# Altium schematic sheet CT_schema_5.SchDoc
size 573 x 363 mm
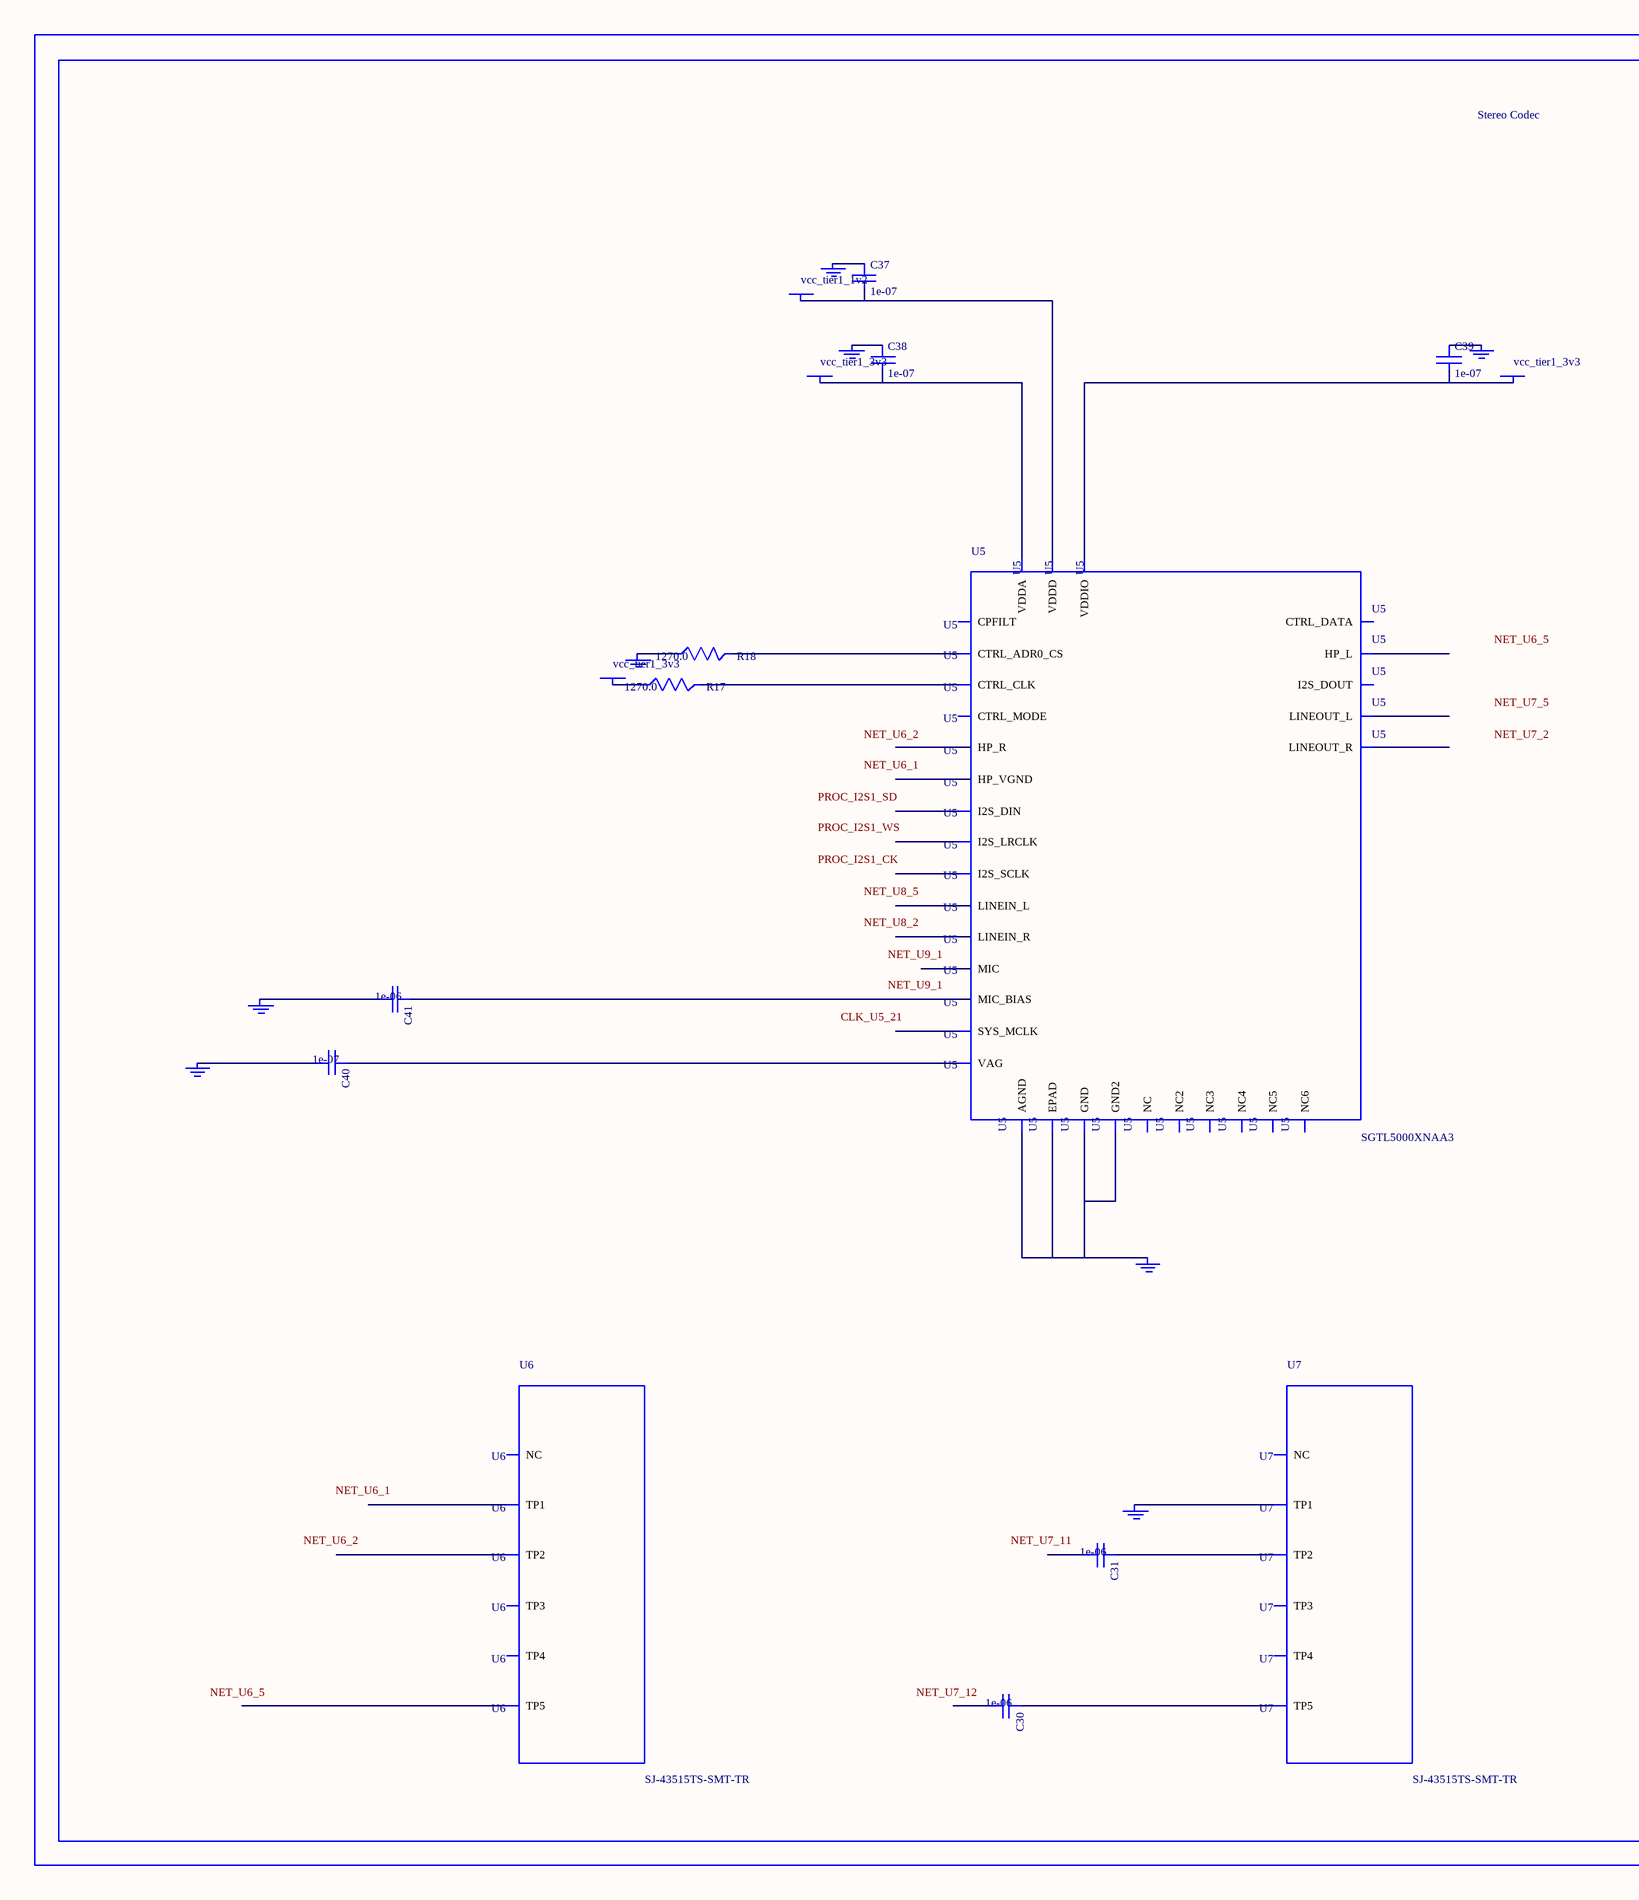
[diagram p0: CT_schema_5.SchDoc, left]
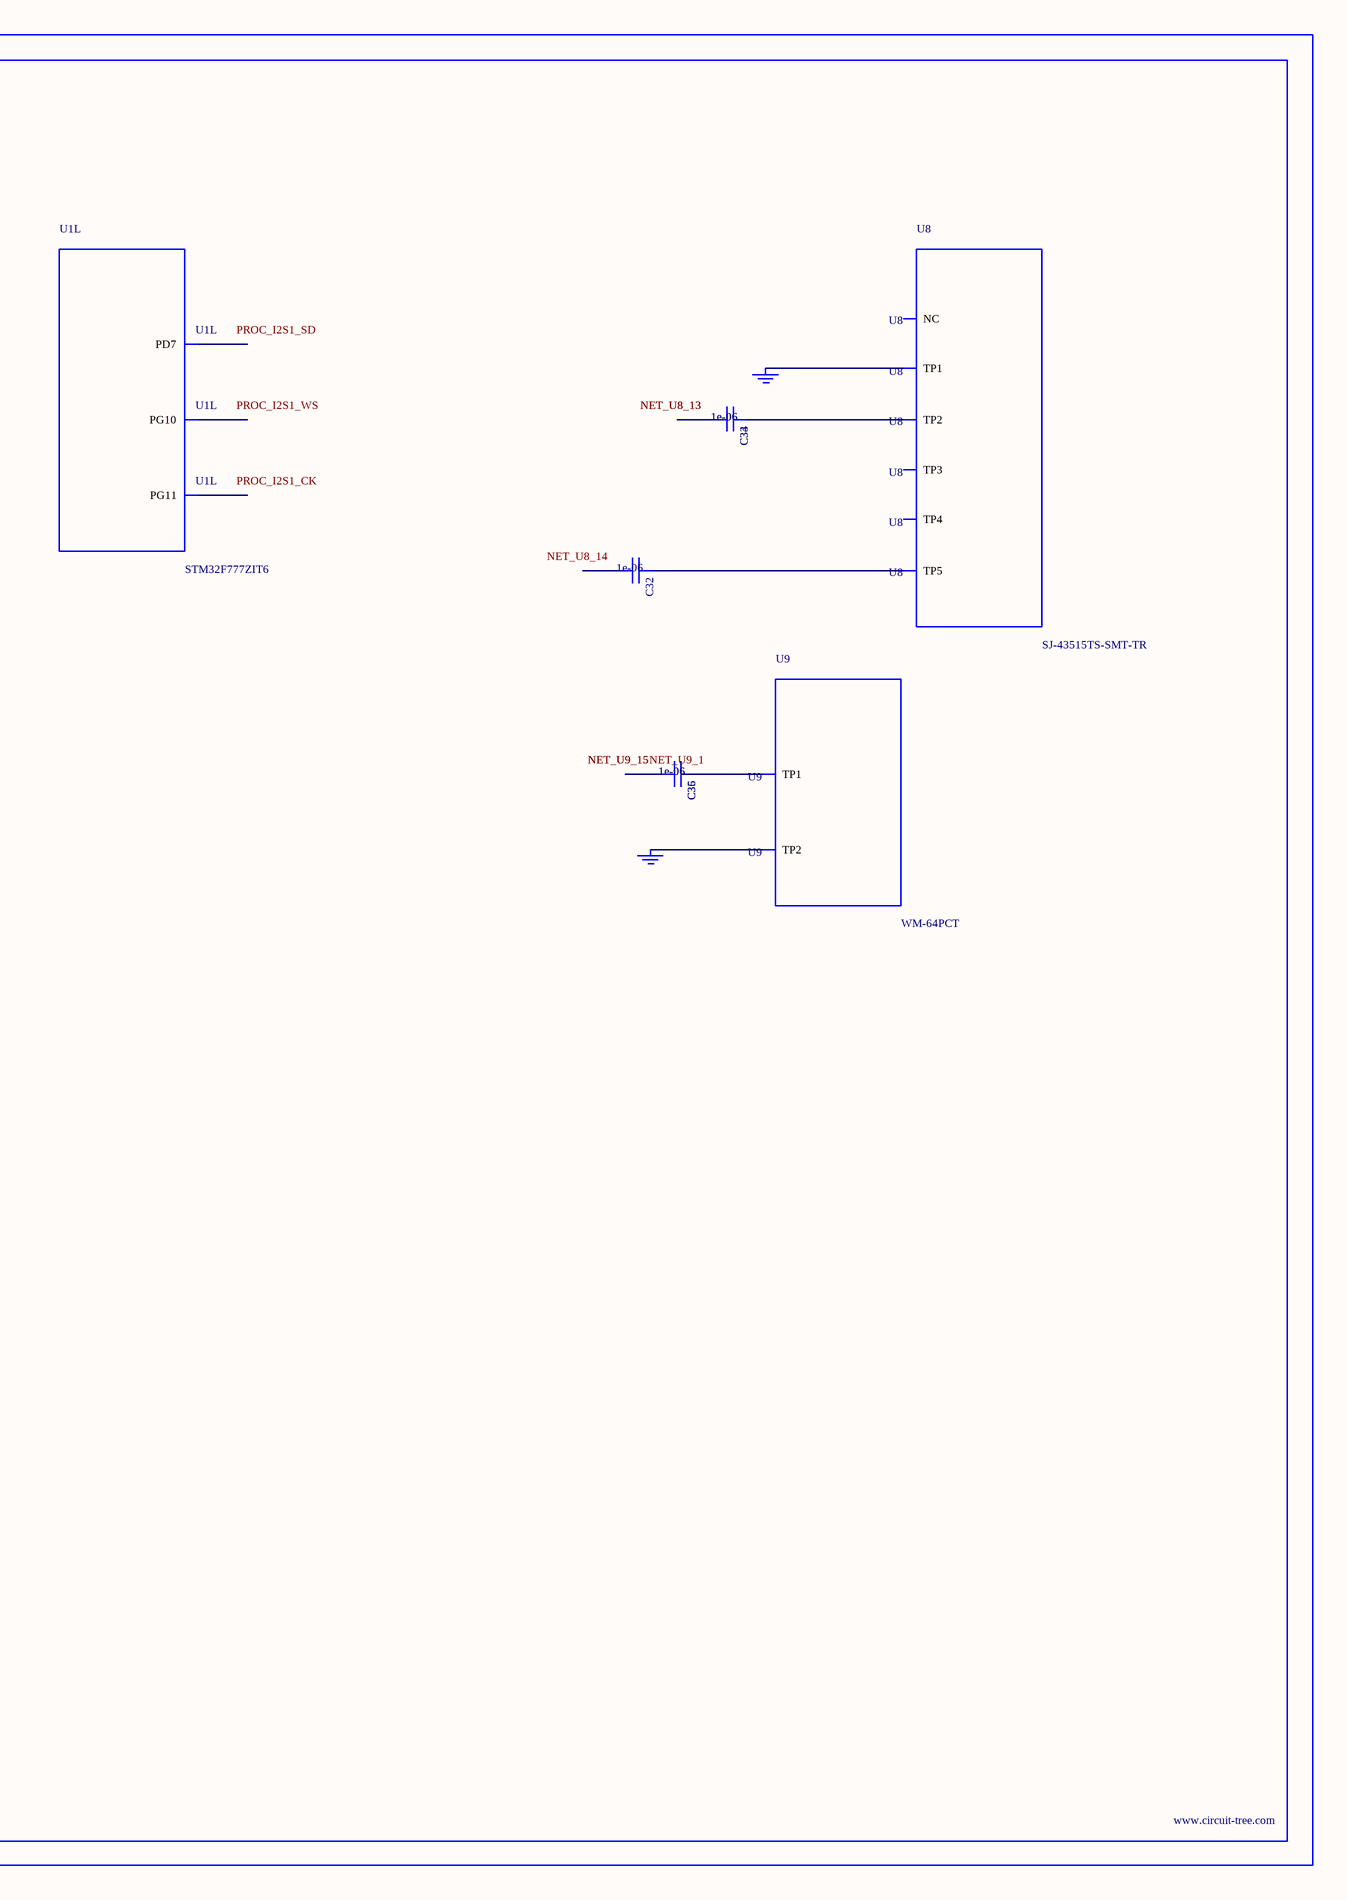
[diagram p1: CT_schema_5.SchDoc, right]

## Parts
BORDER4  (no value)
C30  1e-06  [C0603]
C31  1e-06  [C0603]
C32  1e-06  [C0603]
C33  1e-06  [C0603]
C34  1e-06  [C0603]
C35  1e-06  [C0603]
C36  1e-06  [C0603]
C37  1e-07  [C0402]
C38  1e-07  [C0402]
C39  1e-07  [C0402]
C40  1e-07  [C0402]
C41  1e-06  [C0603]
GND_INSTANCE_4_0  (no value)
GND_INSTANCE_4_1  (no value)
GND_INSTANCE_4_2  (no value)
GND_INSTANCE_4_3  (no value)
GND_INSTANCE_4_4  (no value)
GND_INSTANCE_4_5  (no value)
GND_INSTANCE_4_6  (no value)
GND_INSTANCE_4_7  (no value)
GND_INSTANCE_4_8  (no value)
GND_INSTANCE_4_9  (no value)
GND_INSTANCE_4_10  (no value)
POWER_INSTANCE_4_0  vcc_tier1_3v3
POWER_INSTANCE_4_1  vcc_tier1_3v3
POWER_INSTANCE_4_2  vcc_tier1_3v3
POWER_INSTANCE_4_3  vcc_tier1_1v2
R17  1270.0  [R0603]
R18  1270.0  [R0603]
U1  STM32F777ZIT6  [LQFP144]  (part L of 13)
U5  SGTL5000XNAA3  [QFN-32]
U6  SJ-43515TS-SMT-TR  [SJ-43515TS-SMT-TR]
U7  SJ-43515TS-SMT-TR  [SJ-43515TS-SMT-TR]
U8  SJ-43515TS-SMT-TR  [SJ-43515TS-SMT-TR]
U9  WM-64PCT  [WM-64PC]

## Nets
NetC30_1: C30.1 U7.5(TP5)
NetC31_1: C31.1 U7.2(TP2)
NetC32_1: C32.1 U8.5(TP5)
NetC33_1: C33.1 C34.1 U8.2(TP2)
NetC33_2: C33.2 C34.2
NetC35_1: C35.1 C36.1 U9.1(TP1)
NetC35_2: C35.2 C36.2
NetC37_1: C37.1 GND_INSTANCE_4_5.0(GND)
NetC37_2: C37.2 POWER_INSTANCE_4_3.0(PWR) U5.30(VDDD)
NetC38_1: C38.1 GND_INSTANCE_4_1.0(GND)
NetC38_2: C38.2 POWER_INSTANCE_4_0.0(PWR) U5.5(VDDA)
NetC39_1: C39.1 GND_INSTANCE_4_4.0(GND)
NetC39_2: C39.2 POWER_INSTANCE_4_1.0(PWR) U5.20(VDDIO)
NetC40_1: C40.1 U5.10(VAG)
NetC40_2: C40.2 GND_INSTANCE_4_2.0(GND)
NetC41_1: C41.1 U5.16(MIC_BIAS)
NetC41_2: C41.2 GND_INSTANCE_4_3.0(GND)
NetGND_INSTANCE_4_0_0: GND_INSTANCE_4_0.0(GND) U5.1(GND) U5.3(GND2) U5.7(AGND) U5.EXP(EPAD)
NetGND_INSTANCE_4_6_0: GND_INSTANCE_4_6.0(GND) R18.1
NetGND_INSTANCE_4_7_0: GND_INSTANCE_4_7.0(GND) U7.1(TP1)
NetGND_INSTANCE_4_8_0: GND_INSTANCE_4_8.0(GND) GND_INSTANCE_4_9.0(GND) U8.1(TP1)
NetGND_INSTANCE_4_10_0: GND_INSTANCE_4_10.0(GND) U9.2(TP2)
NetPOWER_INSTANCE_4_2_0: POWER_INSTANCE_4_2.0(PWR) R17.1
NetR17_2: R17.2 U5.29(CTRL_CLK)
NetR18_2: R18.2 U5.31(CTRL_ADR0_CS)

Not connected (* = marked no-connect by the designer): C30 2; C31 2; C32 2; U1 123(PD7) 125(PG10) 126(PG11); U5 2(HP_R) 4(HP_VGND) 6(HP_L) 8(NC) 9(NC2) 11(LINEOUT_R) 12(LINEOUT_L) 13(LINEIN_R) 14(LINEIN_L) 15(MIC) 17(NC3) 18(CPFILT) 19(NC4) 21(SYS_MCLK) 22(NC5) 23(I2S_LRCLK) 24(I2S_SCLK) 25(I2S_DOUT) 26(I2S_DIN) 27(CTRL_DATA) 28(NC6) 32(CTRL_MODE); U6 1(TP1) 2(TP2) 3(TP3) 4(TP4) 5(TP5) 6(NC); U7 3(TP3) 4(TP4) 6(NC); U8 3(TP3) 4(TP4) 6(NC)

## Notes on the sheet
- Labels drawn without touching a wire or pin: CLK_U5_21, NET_U6_1, NET_U6_2, NET_U6_5, NET_U7_2, NET_U7_5, NET_U7_11, NET_U7_12, NET_U8_2, NET_U8_5, NET_U8_14, NET_U9_1, PROC_I2S1_CK, PROC_I2S1_SD, PROC_I2S1_WS

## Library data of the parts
BORDER4 = BORDER_PAGE4
C30-C36 C41 = C0603C105K3RACTU
C37-C40 = C0402C104K3RACTU
GND_INSTANCE_4_0-GND_INSTANCE_4_10 = GND
POWER_INSTANCE_4_0-POWER_INSTANCE_4_3 = PWR
R17 R18 = RC0603FR-071K27L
